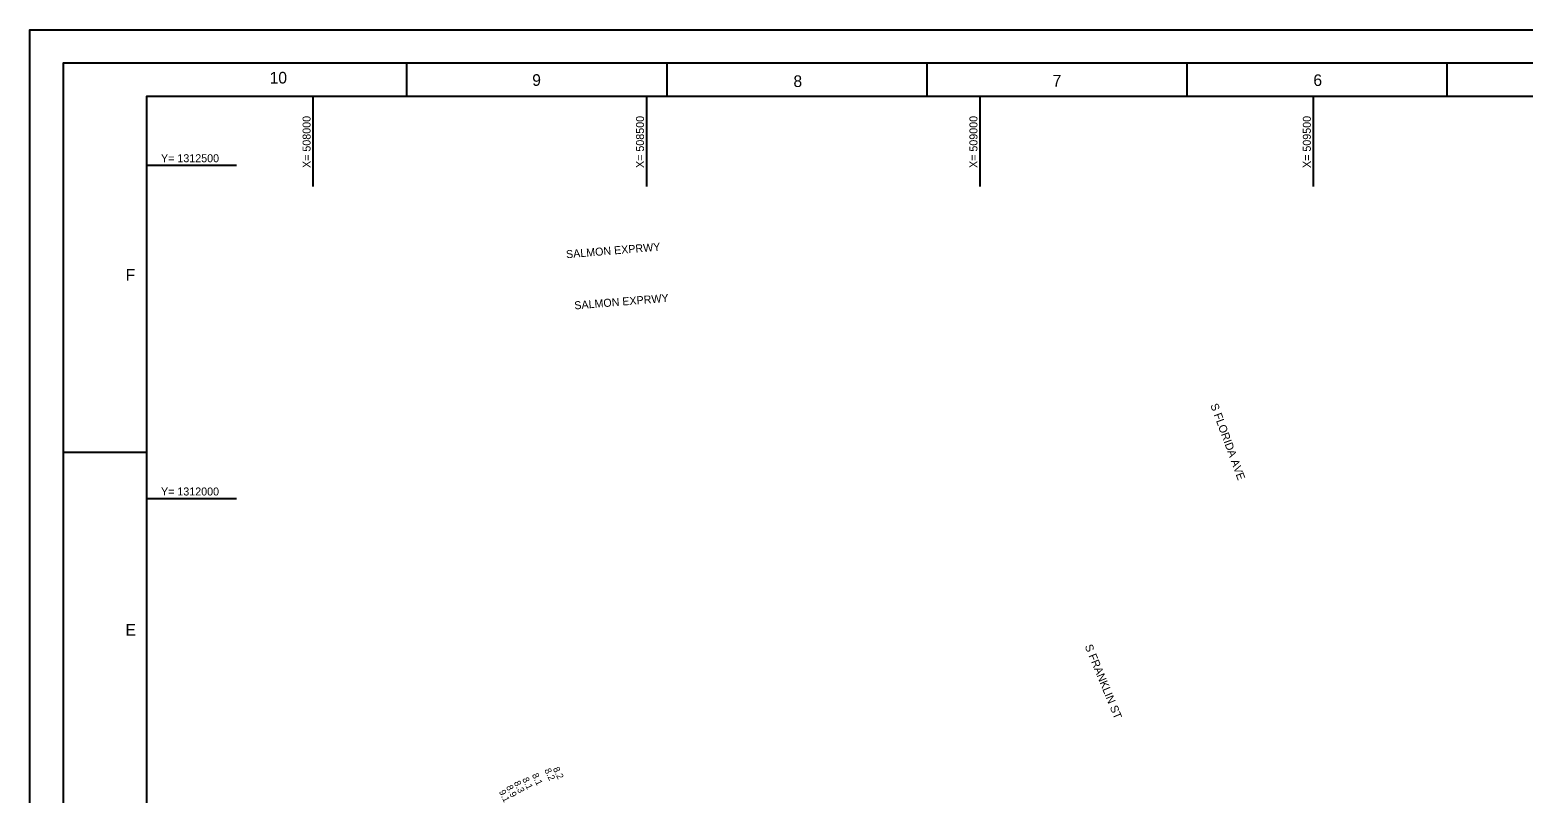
# Model space of a CAD drawing. Extents: x 507575 to 511975, y 1309304 to 1312704.
# Drawn here: x 507575 to 509814, y 1311558 to 1312704 of the extents above; entities that cross this region are included whole.
import ezdxf

# ---------------------------------------------------------------- set-up
doc = ezdxf.new("R2010")
doc.units = 0
for name, color, linetype in [('G-ANNO-NPLT', 7, 'Continuous'), ('G-ANNO-TTLB', 7, 'Continuous'), ('V-ROAD-IDEN', 7, 'Continuous'), ('V-TOPO-COOR-STAT', 7, 'Continuous'), ('V-TOPO-SOUN', 7, 'Continuous')]:
    doc.layers.add(name, color=color, linetype=linetype)

msp = doc.modelspace()

# ---------------------------------------------------------------- linework, layer by layer
at = {"layer": 'G-ANNO-NPLT'}
msp.add_lwpolyline([(507575, 1312703.6), (511975, 1312703.6), (511975, 1309303.7), (507575, 1309303.7)], close=True, dxfattribs=at)
msp.add_lwpolyline([(507575, 1312653.6), (507575, 1312703.6), (507625, 1312703.6)], dxfattribs=at)
at = {"layer": 'G-ANNO-TTLB'}
for p, q in [((508140, 1312653.6), (508140, 1312603.6)), ((508530, 1312653.6), (508530, 1312603.6)), ((508530, 1312653.6), (508530, 1312603.6)), ((508920, 1312653.6), (508920, 1312603.6)), ((509310, 1312653.6), (509310, 1312603.6)), ((509700, 1312653.6), (509700, 1312603.6)), ((507625, 1312070.1), (507750, 1312070.1))]:
    msp.add_line(p, q, dxfattribs=at)
for points in [[(507625, 1309353.7), (511925, 1309353.7), (511925, 1312653.6), (507625, 1312653.6)], [(511875, 1312603.6), (507750, 1312603.6), (507750, 1309403.7), (511875, 1309403.7)]]:
    msp.add_lwpolyline(points, close=True, dxfattribs=at)
at = {"layer": 'V-TOPO-COOR-STAT'}
for p, q in [((508000, 1312468.6), (508000, 1312603.6)), ((508500, 1312468.6), (508500, 1312603.6)), ((509000, 1312468.6), (509000, 1312603.6)), ((509500, 1312468.6), (509500, 1312603.6)), ((507885, 1312500), (507750, 1312500)), ((507885, 1312000), (507750, 1312000))]:
    msp.add_line(p, q, dxfattribs=at)

# ---------------------------------------------------------------- texts
at = {"layer": 'G-ANNO-TTLB'}
for s, p in [('10', (507934.6, 1312623.1)), ('9', (508328.4, 1312619.6)), ('8', (508720.1, 1312617.9)), ('7', (509108.8, 1312618.6)), ('6', (509499.8, 1312619.4)), ('F', (507718.6, 1312327.3)), ('E', (507718.4, 1311794.6))]:
    msp.add_text(s, height=17.5, dxfattribs=at).set_placement(p)
at = {"layer": 'V-ROAD-IDEN'}
for s, rotation, p in [('SALMON EXPRWY', 4.6584, (508379.6, 1312360.9)), ('SALMON EXPRWY', 4.6584, (508392, 1312284.1)), ('S FLORIDA AVE', 290.118, (509345.1, 1312140.6)), ('S FRANKLIN ST', 292.3141, (509156.7, 1311778.8))]:
    msp.add_text(s, height=12, rotation=rotation, dxfattribs=at).set_placement(p)
at = {"layer": 'V-TOPO-COOR-STAT'}
for s, p in [('X= 508000', (507996, 1312496.4)), ('X= 508500', (508496, 1312496.4)), ('X= 509000', (508996, 1312496.4)), ('X= 509500', (509496, 1312496.4))]:
    msp.add_text(s, height=12, rotation=90, dxfattribs=at).set_placement(p)
for s, p in [('Y= 1312500', (507771.7, 1312505)), ('Y= 1312000', (507771.7, 1312005))]:
    msp.add_text(s, height=12, dxfattribs=at).set_placement(p)
at = {"layer": 'V-TOPO-SOUN'}
for s, p in [('8.2', (508346.3, 1311592.9)), ('8.2', (508359.1, 1311595)), ('8.9', (508288.9, 1311567.8)), ('8.3', (508300.5, 1311574.2)), ('8.1', (508313.1, 1311579.4)), ('8.1', (508327.6, 1311585.6)), ('9.1', (508278.2, 1311560.6))]:
    msp.add_text(s, height=10, rotation=295.6464, dxfattribs=at).set_placement(p)

doc.saveas('drawing.dxf')
